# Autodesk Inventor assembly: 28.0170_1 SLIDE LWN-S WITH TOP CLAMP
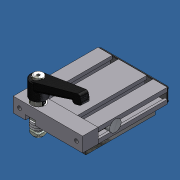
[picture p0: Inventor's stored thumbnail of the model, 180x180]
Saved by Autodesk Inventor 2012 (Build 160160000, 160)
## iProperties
Created: 2007-06
Part Number: 28.0170_1 SLIDE LWN-S WITH TOP CLAMP
Document SubType Name: Assembly
Designer: Andy Moles
Author: Andy Moles
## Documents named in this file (5)
- C:\Andys Backup Data\ANDY'S INVENTOR\INVENTOR LIBRARIES\PARTS LIBRARY\READY FOR USE MODULES LG\28.0170_1 SLIDE LWN-S WITH TOP CLAMP.iam
- C:\Andys Backup Data\ANDY'S INVENTOR\INVENTOR LIBRARIES\PARTS LIBRARY\COMPONENTS LG\22.1096 SLIDE RAIL LN-S.iam
- C:\Andys Backup Data\ANDY'S INVENTOR\INVENTOR LIBRARIES\PARTS LIBRARY\READY FOR USE MODULES LG\SUBCOMPONENTS\28.0237_1 SLIDE LWN-S WITH TOP CLAMP 90X19.ipt
- C:\Andys Backup Data\ANDY'S INVENTOR\INVENTOR LIBRARIES\PARTS LIBRARY\COMPONENTS LR\28.0270_1 SLIDE CLAMPING UNIT FOR SLIDE LWN-S.iam
- C:\Andys Backup Data\ANDY'S INVENTOR\INVENTOR LIBRARIES\PARTS LIBRARY\END CAPS\22.1014_1 END CAP 90X19 GRAY.ipt
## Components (5 placed, 4 different names)
1. 28.0237_1 SLIDE LWN-S WITH TOP CLAMP 90X19:1 — Insert:1, Angle:1, Mate:1, Insert:2, Angle:2, Mate:5, Mate:6, Mate:7, Flush:5, Flush:6, Mate:8, Flush:7, Flush:8
2. 22.1096 SLIDE RAIL LN-S:1 [sub-assembly] — Insert:1, Angle:1, Mate:4
3. 22.1096 SLIDE RAIL LN-S:2 [sub-assembly] — Mate:1, Insert:2, Angle:2
4. 22.1014_1 END CAP 90X19 GRAY:1 — Mate:8, Flush:7, Flush:8
5. 28.0270_1 SLIDE CLAMPING UNIT FOR SLIDE LWN-S:1 [sub-assembly] — Mate:7, Flush:5, Flush:6
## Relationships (14: Mate 6, Flush 4, Insert 2, Angle 2)
- Insert:1: 28.0237_1 SLIDE LWN-S WITH TOP CLAMP 90X19:1 ↔ 22.1096 SLIDE RAIL LN-S:1
- Angle:1: 28.0237_1 SLIDE LWN-S WITH TOP CLAMP 90X19:1 ↔ 22.1096 SLIDE RAIL LN-S:1
- Mate:1: 28.0237_1 SLIDE LWN-S WITH TOP CLAMP 90X19:1 ↔ 22.1096 SLIDE RAIL LN-S:2
- Insert:2: 28.0237_1 SLIDE LWN-S WITH TOP CLAMP 90X19:1 ↔ 22.1096 SLIDE RAIL LN-S:2
- Angle:2: 28.0237_1 SLIDE LWN-S WITH TOP CLAMP 90X19:1 ↔ 22.1096 SLIDE RAIL LN-S:2
- Mate:4: 22.1096 SLIDE RAIL LN-S:1
- Mate:5: 28.0237_1 SLIDE LWN-S WITH TOP CLAMP 90X19:1
- Mate:6: 28.0237_1 SLIDE LWN-S WITH TOP CLAMP 90X19:1
- Mate:7: 28.0237_1 SLIDE LWN-S WITH TOP CLAMP 90X19:1 ↔ 28.0270_1 SLIDE CLAMPING UNIT FOR SLIDE LWN-S:1
- Flush:5: 28.0237_1 SLIDE LWN-S WITH TOP CLAMP 90X19:1 ↔ 28.0270_1 SLIDE CLAMPING UNIT FOR SLIDE LWN-S:1
- Flush:6: 28.0237_1 SLIDE LWN-S WITH TOP CLAMP 90X19:1 ↔ 28.0270_1 SLIDE CLAMPING UNIT FOR SLIDE LWN-S:1
- Mate:8: 28.0237_1 SLIDE LWN-S WITH TOP CLAMP 90X19:1 ↔ 22.1014_1 END CAP 90X19 GRAY:1
- Flush:7: 28.0237_1 SLIDE LWN-S WITH TOP CLAMP 90X19:1 ↔ 22.1014_1 END CAP 90X19 GRAY:1
- Flush:8: 28.0237_1 SLIDE LWN-S WITH TOP CLAMP 90X19:1 ↔ 22.1014_1 END CAP 90X19 GRAY:1
